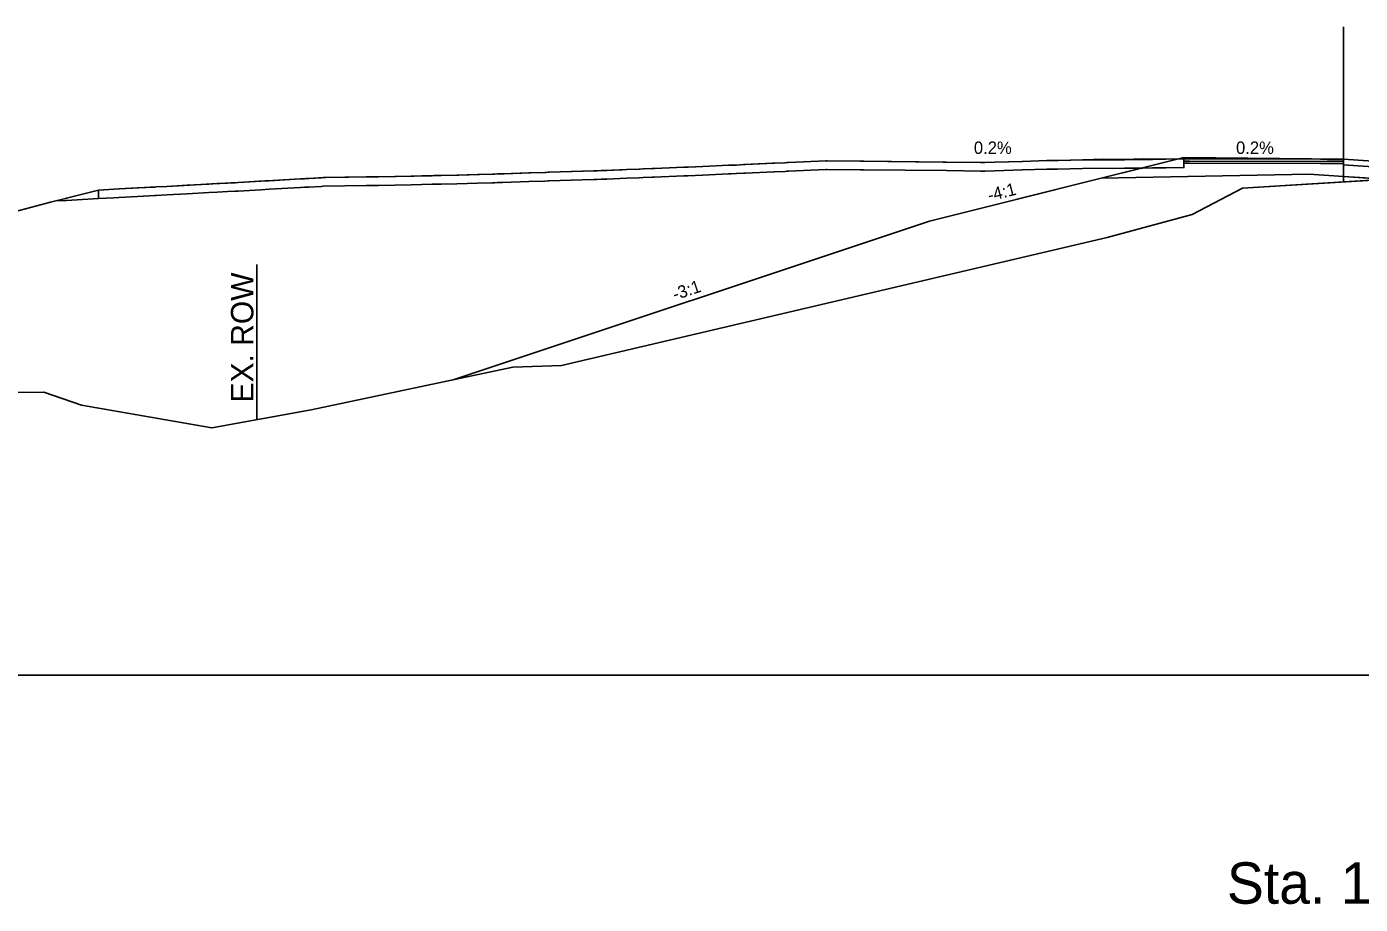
# Model space of a CAD drawing. Extents: x -26 to 5403, y -13 to 9553.
# Drawn here: x 4111.7 to 4189, y 1986.7 to 2037.6 of the extents above; entities that cross this region are included whole.
import ezdxf

# ---------------------------------------------------------------- set-up
doc = ezdxf.new("R2010")
doc.units = 0
for name, color, linetype in [('CONST_DCH', 7, 'Continuous'), ('CONST_LV3', 7, 'Continuous'), ('Draft_XS_Text', 7, 'Continuous'), ('DTM_P_FINISHED_GRADE', 7, 'Continuous'), ('DTM_X_GROUND', 7, 'Continuous'), ('SLOPE_STAKES_FILL', 7, 'Continuous'), ('TRANS_EOP_PAVED', 7, 'Continuous'), ('X_ROW', 7, 'Continuous'), ('XS_CELL', 7, 'Continuous'), ('XS_M_SHAPES_EARTHWORK', 7, 'Continuous'), ('XS_P_ASPHALT', 7, 'Continuous'), ('XS_P_DR_ASPHALT', 7, 'Continuous'), ('XS_P_DR_ASPHALT_B', 7, 'Continuous'), ('XS_P_DR_GRAVEL', 7, 'Continuous'), ('XS_P_GROUND', 7, 'Continuous'), ('XS_P_SHOULDER', 7, 'Continuous'), ('XS_P_SUBGRADE_GRANULAR', 7, 'Continuous'), ('XS_P_TX_FS_BS', 7, 'Continuous')]:
    doc.layers.add(name, color=color, linetype=linetype)

msp = doc.modelspace()

# ---------------------------------------------------------------- linework, layer by layer
at = {"layer": 'CONST_LV3'}
for points in [[(4115.815, 2028.117), (4116.722, 2028.167), (4117.042, 2028.185), (4118.141, 2028.246), (4119.162, 2028.296), (4119.782, 2028.33), (4121.119, 2028.406), (4122.374, 2028.474), (4122.85, 2028.497), (4123.485, 2028.534), (4123.916, 2028.555), (4125.472, 2028.644), (4125.924, 2028.67), (4127.833, 2028.778), (4128.015, 2028.788), (4128.028, 2028.788), (4128.841, 2028.835), (4128.979, 2028.837), (4128.996, 2028.837), (4129.007, 2028.837), (4131.686, 2028.879), (4131.846, 2028.883), (4132.056, 2028.888), (4134.114, 2028.925), (4134.734, 2028.939), (4135.317, 2028.951), (4135.419, 2028.957), (4135.69, 2028.965), (4136.714, 2028.987), (4137.916, 2029.023), (4138.772, 2029.043), (4138.955, 2029.054), (4139.329, 2029.064), (4140.858, 2029.117), (4141.76, 2029.142), (4141.952, 2029.148), (4142.581, 2029.166), (4143.274, 2029.186), (4144.574, 2029.232), (4144.755, 2029.237), (4145.002, 2029.246), (4146.172, 2029.293), (4146.457, 2029.302), (4147.188, 2029.331), (4147.423, 2029.339), (4147.952, 2029.361), (4148.054, 2029.364), (4149.783, 2029.436), (4150.001, 2029.444), (4150.851, 2029.484), (4152.351, 2029.549), (4152.488, 2029.554), (4152.79, 2029.568), (4153.22, 2029.593), (4153.235, 2029.594), (4154.895, 2029.668), (4154.985, 2029.671), (4155.598, 2029.699), (4155.624, 2029.7), (4155.733, 2029.709), (4155.829, 2029.713), (4157.984, 2029.808), (4158.068, 2029.808), (4159.985, 2029.789), (4164.759, 2029.742), (4164.985, 2029.739), (4166.972, 2029.72), (4167.204, 2029.718), (4167.796, 2029.733), (4169.381, 2029.78), (4170.793, 2029.83), (4171.452, 2029.823), (4172.918, 2029.867), (4174.075, 2029.905), (4175.262, 2029.893), (4176.414, 2029.921), (4186.669, 2029.904), (4187.048, 2029.907), (4188, 2029.907)], [(4173.949, 2028.805), (4164, 2026.317)]]:
    msp.add_lwpolyline(points, dxfattribs=at)
at = {"layer": 'DTM_P_FINISHED_GRADE'}
for points in [[(4115.815, 2028.117), (4116.701, 2028.166), (4117.005, 2028.183), (4118.078, 2028.242), (4119.081, 2028.292), (4119.162, 2028.296), (4119.782, 2028.33), (4120.965, 2028.398), (4122.217, 2028.465), (4122.695, 2028.488), (4123.303, 2028.523), (4123.741, 2028.544), (4123.916, 2028.555), (4125.231, 2028.631), (4125.707, 2028.658), (4127.539, 2028.762), (4127.771, 2028.774), (4128.015, 2028.788), (4128.719, 2028.828), (4128.721, 2028.828), (4128.728, 2028.829), (4128.741, 2028.829), (4128.844, 2028.835), (4131.336, 2028.873), (4131.483, 2028.875), (4131.634, 2028.88), (4131.846, 2028.883), (4132.056, 2028.888), (4133.953, 2028.922), (4134.566, 2028.936), (4135.165, 2028.948), (4135.266, 2028.954), (4135.419, 2028.957), (4135.69, 2028.965), (4136.587, 2028.984), (4137.787, 2029.02), (4138.665, 2029.041), (4138.772, 2029.043), (4138.955, 2029.054), (4139.231, 2029.061), (4140.765, 2029.115), (4141.687, 2029.14), (4141.879, 2029.146), (4141.952, 2029.148), (4142.581, 2029.166), (4143.216, 2029.184), (4144.523, 2029.23), (4144.707, 2029.236), (4144.955, 2029.244), (4145.002, 2029.246), (4145.286, 2029.255), (4146.42, 2029.301), (4147.154, 2029.33), (4147.392, 2029.338), (4147.923, 2029.36), (4147.952, 2029.361), (4148.027, 2029.363), (4149.762, 2029.435), (4149.982, 2029.443), (4150.835, 2029.483), (4150.851, 2029.484), (4152.351, 2029.549), (4152.476, 2029.554), (4152.779, 2029.567), (4152.801, 2029.568), (4153.23, 2029.594), (4153.235, 2029.594), (4153.329, 2029.598), (4154.976, 2029.671), (4155.011, 2029.672), (4155.624, 2029.7), (4155.733, 2029.709), (4155.829, 2029.713), (4157.984, 2029.808), (4158.058, 2029.808), (4159.975, 2029.789), (4159.985, 2029.789), (4160.19, 2029.787), (4164.975, 2029.74), (4166.962, 2029.72), (4167.193, 2029.718), (4167.785, 2029.733), (4169.364, 2029.78), (4169.381, 2029.78), (4170.793, 2029.83), (4171.423, 2029.823), (4172.872, 2029.867), (4175.295, 2029.876), (4175.578, 2029.88), (4175.926, 2029.884), (4176.364, 2029.889), (4176.93, 2029.896), (4177.691, 2029.905), (4178.739, 2029.917)], [(4178.739, 2029.917), (4178.921, 2029.917), (4179.061, 2029.917), (4186.669, 2029.904), (4187.048, 2029.907), (4188, 2029.907)]]:
    msp.add_lwpolyline(points, dxfattribs=at)
at = {"layer": 'DTM_X_GROUND'}
msp.add_lwpolyline([(4100.059, 2016.348), (4112.646, 2016.393), (4114.832, 2015.642), (4122.383, 2014.331), (4128.141, 2015.372), (4139.845, 2017.844), (4142.655, 2017.942), (4174.303, 2025.362), (4179.23, 2026.707), (4182.13, 2028.223), (4191.292, 2028.789), (4191.451, 2028.798), (4191.721, 2028.784), (4201.141, 2028.301), (4206.784, 2027.991), (4211.018, 2027.787), (4216.675, 2026.868), (4219.277, 2026.399), (4228.386, 2022.816), (4231.249, 2021.244), (4249.214, 2017.376), (4252.293, 2017.002), (4258.798, 2015.908)], dxfattribs=at)
at = {"layer": 'TRANS_EOP_PAVED'}
msp.add_line((4188, 2037.586), (4188, 2028.586), dxfattribs=at)
at = {"layer": 'X_ROW'}
msp.add_line((4125, 2023.804), (4125, 2014.804), dxfattribs=at)
at = {"layer": 'XS_CELL'}
msp.add_line((4000, 2000), (4200, 2000), dxfattribs=at)
at = {"layer": 'XS_M_SHAPES_EARTHWORK'}
msp.add_lwpolyline([(4100.059, 2016.348), (4112.646, 2016.393), (4114.832, 2015.642), (4122.383, 2014.331), (4128.141, 2015.372), (4139.845, 2017.844), (4142.655, 2017.942), (4174.303, 2025.362), (4179.23, 2026.707), (4182.13, 2028.223), (4190.497, 2028.74), (4188, 2028.91), (4186, 2029.046), (4173.949, 2028.805), (4176.283, 2029.388), (4175.926, 2029.384), (4175.578, 2029.38), (4175.295, 2029.376), (4172.872, 2029.367), (4171.423, 2029.323), (4170.793, 2029.33), (4169.381, 2029.28), (4169.364, 2029.28), (4167.785, 2029.233), (4167.193, 2029.218), (4166.962, 2029.22), (4164.975, 2029.24), (4160.19, 2029.287), (4159.985, 2029.289), (4159.975, 2029.289), (4158.058, 2029.308), (4157.984, 2029.308), (4155.829, 2029.213), (4155.733, 2029.209), (4155.624, 2029.2), (4155.011, 2029.172), (4154.976, 2029.171), (4153.329, 2029.098), (4153.235, 2029.094), (4153.23, 2029.094), (4152.801, 2029.068), (4152.779, 2029.067), (4152.476, 2029.054), (4152.351, 2029.049), (4150.851, 2028.984), (4150.835, 2028.983), (4149.982, 2028.943), (4149.762, 2028.935), (4148.027, 2028.863), (4147.952, 2028.861), (4147.923, 2028.86), (4147.392, 2028.838), (4147.154, 2028.83), (4146.42, 2028.801), (4145.286, 2028.755), (4145.002, 2028.746), (4144.955, 2028.744), (4144.707, 2028.736), (4144.523, 2028.73), (4143.216, 2028.684), (4142.581, 2028.666), (4141.952, 2028.648), (4141.879, 2028.646), (4141.687, 2028.64), (4140.765, 2028.615), (4139.231, 2028.561), (4138.955, 2028.554), (4138.772, 2028.543), (4138.665, 2028.541), (4137.787, 2028.52), (4136.587, 2028.484), (4135.69, 2028.465), (4135.419, 2028.457), (4135.266, 2028.454), (4135.165, 2028.448), (4134.566, 2028.436), (4133.953, 2028.422), (4132.056, 2028.388), (4131.846, 2028.383), (4131.634, 2028.38), (4131.483, 2028.375), (4131.336, 2028.373), (4128.844, 2028.335), (4128.741, 2028.329), (4128.728, 2028.329), (4128.721, 2028.328), (4128.719, 2028.328), (4128.015, 2028.288), (4127.771, 2028.274), (4127.539, 2028.262), (4125.707, 2028.158), (4125.231, 2028.131), (4123.916, 2028.055), (4123.741, 2028.044), (4123.303, 2028.023), (4122.695, 2027.988), (4122.217, 2027.965), (4120.965, 2027.898), (4119.782, 2027.83), (4119.162, 2027.796), (4119.081, 2027.792), (4118.078, 2027.742), (4117.005, 2027.683), (4116.701, 2027.666), (4115.815, 2027.617), (4113.96, 2027.516), (4113.349, 2027.492), (4113.339, 2027.49), (4113.029, 2027.41), (4109.543, 2026.479)], dxfattribs=at)
at = {"layer": 'XS_P_ASPHALT'}
msp.add_lwpolyline([(4200, 2029.094), (4212, 2028.278), (4212, 2027.944), (4200, 2028.76), (4188, 2029.576), (4188, 2029.91), (4200, 2029.094)], dxfattribs=at)
at = {"layer": 'XS_P_DR_ASPHALT'}
msp.add_lwpolyline([(4178.739, 2029.917), (4178.739, 2029.792), (4178.921, 2029.792), (4179.061, 2029.792), (4186.669, 2029.779), (4187.048, 2029.782), (4188, 2029.782), (4188, 2029.907), (4187.048, 2029.907), (4186.669, 2029.904), (4179.061, 2029.917), (4178.921, 2029.917), (4178.739, 2029.917)], dxfattribs=at)
at = {"layer": 'XS_P_DR_ASPHALT_B'}
msp.add_lwpolyline([(4178.739, 2029.792), (4178.739, 2029.667), (4178.921, 2029.667), (4179.061, 2029.667), (4186.669, 2029.654), (4187.048, 2029.657), (4188, 2029.657), (4188, 2029.782), (4187.048, 2029.782), (4186.669, 2029.779), (4179.061, 2029.792), (4178.921, 2029.792), (4178.739, 2029.792)], dxfattribs=at)
at = {"layer": 'XS_P_DR_GRAVEL'}
for points in [[(4115.815, 2028.117), (4115.815, 2027.617), (4116.701, 2027.666), (4117.005, 2027.683), (4118.078, 2027.742), (4119.081, 2027.792), (4119.162, 2027.796), (4119.782, 2027.83), (4120.965, 2027.898), (4122.217, 2027.965), (4122.695, 2027.988), (4123.303, 2028.023), (4123.741, 2028.044), (4123.916, 2028.055), (4125.231, 2028.131), (4125.707, 2028.158), (4127.539, 2028.262), (4127.771, 2028.274), (4128.015, 2028.288), (4128.719, 2028.328), (4128.721, 2028.328), (4128.728, 2028.329), (4128.741, 2028.329), (4128.844, 2028.335), (4131.336, 2028.373), (4131.483, 2028.375), (4131.634, 2028.38), (4131.846, 2028.383), (4132.056, 2028.388), (4133.953, 2028.422), (4134.566, 2028.436), (4135.165, 2028.448), (4135.266, 2028.454), (4135.419, 2028.457), (4135.69, 2028.465), (4136.587, 2028.484), (4137.787, 2028.52), (4138.665, 2028.541), (4138.772, 2028.543), (4138.955, 2028.554), (4139.231, 2028.561), (4140.765, 2028.615), (4141.687, 2028.64), (4141.879, 2028.646), (4141.952, 2028.648), (4142.581, 2028.666), (4143.216, 2028.684), (4144.523, 2028.73), (4144.707, 2028.736), (4144.955, 2028.744), (4145.002, 2028.746), (4145.286, 2028.755), (4146.42, 2028.801), (4147.154, 2028.83), (4147.392, 2028.838), (4147.923, 2028.86), (4147.952, 2028.861), (4148.027, 2028.863), (4149.762, 2028.935), (4149.982, 2028.943), (4150.835, 2028.983), (4150.851, 2028.984), (4152.351, 2029.049), (4152.476, 2029.054), (4152.779, 2029.067), (4152.801, 2029.068), (4153.23, 2029.094), (4153.235, 2029.094), (4153.329, 2029.098), (4154.976, 2029.171), (4155.011, 2029.172), (4155.624, 2029.2), (4155.733, 2029.209), (4155.829, 2029.213), (4157.984, 2029.308), (4158.058, 2029.308), (4159.975, 2029.289), (4159.985, 2029.289), (4160.19, 2029.287), (4164.975, 2029.24), (4166.962, 2029.22), (4167.193, 2029.218), (4167.785, 2029.233), (4169.364, 2029.28), (4169.381, 2029.28), (4170.793, 2029.33), (4171.423, 2029.323), (4172.872, 2029.367), (4175.295, 2029.376), (4175.578, 2029.38), (4175.926, 2029.384), (4176.364, 2029.389), (4176.93, 2029.396), (4177.691, 2029.405), (4178.739, 2029.417), (4178.739, 2029.917), (4177.691, 2029.905), (4176.93, 2029.896), (4176.364, 2029.889), (4175.926, 2029.884), (4175.578, 2029.88), (4175.295, 2029.876), (4172.872, 2029.867), (4171.423, 2029.823), (4170.793, 2029.83), (4169.381, 2029.78), (4169.364, 2029.78), (4167.785, 2029.733), (4167.193, 2029.718), (4166.962, 2029.72), (4164.975, 2029.74), (4160.19, 2029.787), (4159.985, 2029.789), (4159.975, 2029.789), (4158.058, 2029.808), (4157.984, 2029.808), (4155.829, 2029.713), (4155.733, 2029.709), (4155.624, 2029.7), (4155.011, 2029.672), (4154.976, 2029.671), (4153.329, 2029.598), (4153.235, 2029.594), (4153.23, 2029.594), (4152.801, 2029.568), (4152.779, 2029.567), (4152.476, 2029.554), (4152.351, 2029.549), (4150.851, 2029.484), (4150.835, 2029.483), (4149.982, 2029.443), (4149.762, 2029.435), (4148.027, 2029.363), (4147.952, 2029.361), (4147.923, 2029.36), (4147.392, 2029.338), (4147.154, 2029.33), (4146.42, 2029.301), (4145.286, 2029.255), (4145.002, 2029.246), (4144.955, 2029.244), (4144.707, 2029.236), (4144.523, 2029.23), (4143.216, 2029.184), (4142.581, 2029.166), (4141.952, 2029.148), (4141.879, 2029.146), (4141.687, 2029.14), (4140.765, 2029.115), (4139.231, 2029.061), (4138.955, 2029.054), (4138.772, 2029.043), (4138.665, 2029.041), (4137.787, 2029.02), (4136.587, 2028.984), (4135.69, 2028.965), (4135.419, 2028.957), (4135.266, 2028.954), (4135.165, 2028.948), (4134.566, 2028.936), (4133.953, 2028.922), (4132.056, 2028.888), (4131.846, 2028.883), (4131.634, 2028.88), (4131.483, 2028.875), (4131.336, 2028.873), (4128.844, 2028.835), (4128.741, 2028.829), (4128.728, 2028.829), (4128.721, 2028.828), (4128.719, 2028.828), (4128.015, 2028.788), (4127.771, 2028.774), (4127.539, 2028.762), (4125.707, 2028.658), (4125.231, 2028.631), (4123.916, 2028.555), (4123.741, 2028.544), (4123.303, 2028.523), (4122.695, 2028.488), (4122.217, 2028.465), (4120.965, 2028.398), (4119.782, 2028.33), (4119.162, 2028.296), (4119.081, 2028.292), (4118.078, 2028.242), (4117.005, 2028.183), (4116.701, 2028.166), (4115.815, 2028.117)], [(4115.815, 2027.617), (4113.96, 2027.516), (4113.349, 2027.492)]]:
    msp.add_lwpolyline(points, dxfattribs=at)
at = {"layer": 'XS_P_GROUND'}
for points in [[(4178.739, 2030.002), (4164, 2026.317), (4136.381, 2017.112)], [(4115.815, 2028.117), (4113.96, 2027.642), (4113.924, 2027.634), (4113.339, 2027.49), (4113.029, 2027.41), (4109.543, 2026.479)]]:
    msp.add_lwpolyline(points, dxfattribs=at)
at = {"layer": 'XS_P_SHOULDER'}
msp.add_lwpolyline([(4188, 2029.91), (4178.739, 2030.002)], dxfattribs=at)
at = {"layer": 'XS_P_SUBGRADE_GRANULAR'}
for points in [[(4188, 2028.91), (4186, 2029.046), (4173.949, 2028.805)], [(4200, 2028.094), (4188, 2028.91)]]:
    msp.add_lwpolyline(points, dxfattribs=at)

# ---------------------------------------------------------------- texts
at = {"layer": 'CONST_DCH'}
msp.add_text('X', height=0.012, dxfattribs=at).set_placement((4136.378, 2017.106))
at = {"layer": 'Draft_XS_Text'}
msp.add_text('Sta. 141+87.5000 R1', height=2.4, dxfattribs=at).set_placement((4181.236, 1986.75))
at = {"layer": 'SLOPE_STAKES_FILL'}
msp.add_text('X', height=0.012, dxfattribs=at).set_placement((4136.378, 2017.106))
at = {"layer": 'X_ROW'}
msp.add_text('EX. ROW', height=1.3, rotation=90, dxfattribs=at).set_placement((4124.8, 2015.804))
at = {"layer": 'XS_P_ASPHALT'}
msp.add_text('X', height=0.012, dxfattribs=at).set_placement((4187.996, 2029.904))
at = {"layer": 'XS_P_GROUND'}
msp.add_text('X', height=0.012, dxfattribs=at).set_placement((4163.996, 2026.311))
at = {"layer": 'XS_P_SHOULDER'}
msp.add_text('X', height=0.012, dxfattribs=at).set_placement((4178.736, 2029.996))
at = {"layer": 'XS_P_TX_FS_BS'}
for s, rotation, p in [('0.2%', 359.90441, (4166.564, 2030.212)), ('0.2%', 359.90441, (4181.763, 2030.212)), ('-4:1', 14.03624, (4167.463, 2027.453)), ('-3:1', 18.43323, (4149.235, 2021.713))]:
    msp.add_text(s, height=0.72, rotation=rotation, dxfattribs=at).set_placement(p)

doc.saveas('drawing.dxf')
